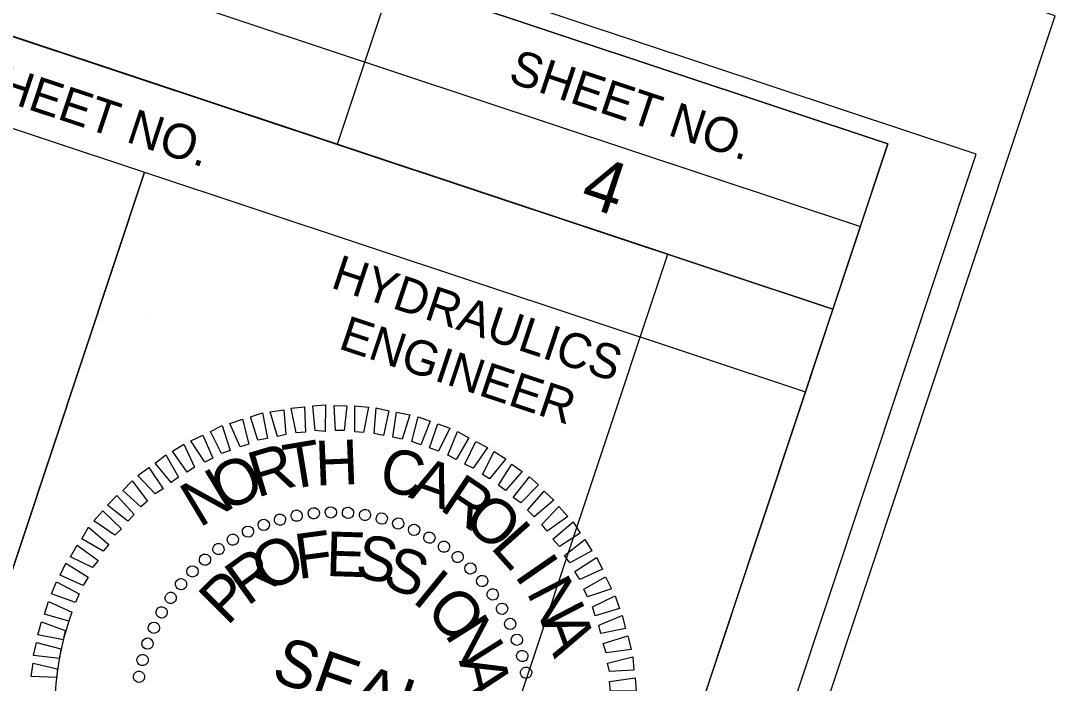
# Model space of a CAD drawing. Extents: x 2296288 to 2297455, y 600637 to 601606.
# Drawn here: x 2297365.9 to 2297455, y 601229.6 to 601286.7 of the extents above; entities that cross this region are included whole.
import ezdxf

# ---------------------------------------------------------------- set-up
doc = ezdxf.new("R2010")
doc.units = 0
for name, color, linetype in [('Exist DTM Crownline Cogo Point CELL', 7, 'Continuous'), ('Exist DTM Drainline Cogo Comment', 7, 'Continuous'), ('Exist DTM Drainline Cogo Point CELL', 7, 'Continuous'), ('Exist Roads Curbs Cogo Number', 7, 'Continuous'), ('Exist Roads Curbs Cogo Point CELL', 7, 'Continuous'), ('Exist Roads EOP Cogo Point CELL', 7, 'Continuous'), ('Exist Roads EOP Other Cogo Elevation', 7, 'Continuous')]:
    doc.layers.add(name, color=color, linetype=linetype)

msp = doc.modelspace()

# ---------------------------------------------------------------- linework, layer by layer
at = {"layer": 'Exist DTM Crownline Cogo Point CELL'}
msp.add_arc((2297392.802, 601227.377), 23.962, 161.60824, 341.60824, dxfattribs=at)
at = {"layer": 'Exist DTM Drainline Cogo Comment'}
for p, q in [((2297324.329, 601306.788), (2297438.228, 601268.917)), ((2297321.963, 601299.671), (2297435.862, 601261.8)), ((2297321.963, 601299.671), (2297435.862, 601261.8)), ((2297397.893, 601290.232), (2297393.16, 601275.998)), ((2297435.862, 601261.8), (2297433.495, 601254.683))]:
    msp.add_line(p, q, dxfattribs=at)
for points in [[(2297440.604, 601276.062), (2296586.575, 601560.023), (2296387.802, 600962.203), (2297241.831, 600678.242)], [(2297326.705, 601313.933), (2297440.604, 601276.062), (2297435.862, 601261.8), (2297321.963, 601299.671)], [(2297319.596, 601292.554), (2297376.56, 601273.614), (2297355.263, 601209.561), (2297298.299, 601228.501)], [(2297376.56, 601273.614), (2297433.496, 601254.683), (2297412.199, 601190.63), (2297355.263, 601209.561)]]:
    msp.add_lwpolyline(points, close=True, dxfattribs=at)
at = {"layer": 'Exist DTM Drainline Cogo Point CELL'}
msp.add_lwpolyline([(2297421.637, 601266.561), (2296596.076, 601541.057), (2296406.768, 600971.704), (2297232.33, 600697.208)], close=True, dxfattribs=at)
at = {"layer": 'Exist Roads Curbs Cogo Number'}
msp.add_lwpolyline([(2297455.016, 601287.078), (2296496.225, 601605.872), (2296287.987, 600979.583), (2297246.777, 600660.79)], close=True, dxfattribs=at)
at = {"layer": 'Exist Roads Curbs Cogo Point CELL'}
msp.add_lwpolyline([(2297448.204, 601275.148), (2296499.377, 601590.629), (2296299.639, 600989.904), (2297248.465, 600674.423)], close=True, dxfattribs=at)
at = {"layer": 'Exist Roads EOP Other Cogo Elevation'}
for p, q in [((2297376.853, 601260.92), (2297376.853, 601260.92)), ((2297391.156, 601244.25), (2297391.156, 601244.25)), ((2297392.608, 601244.336), (2297392.608, 601244.336)), ((2297394.08, 601244.273), (2297394.08, 601244.273)), ((2297388.232, 601243.692), (2297388.232, 601243.692)), ((2297389.694, 601244.024), (2297389.694, 601244.024)), ((2297395.575, 601244.061), (2297395.575, 601244.061)), ((2297397.016, 601243.795), (2297397.016, 601243.795)), ((2297398.436, 601243.359), (2297398.436, 601243.359)), ((2297385.469, 601242.655), (2297385.469, 601242.655)), ((2297386.845, 601243.264), (2297386.845, 601243.264)), ((2297399.813, 601242.794), (2297399.813, 601242.794)), ((2297384.178, 601241.982), (2297384.178, 601241.982)), ((2297401.115, 601242.112), (2297401.115, 601242.112)), ((2297382.941, 601241.148), (2297382.941, 601241.148)), ((2297402.365, 601241.376), (2297402.365, 601241.376)), ((2297381.757, 601240.262), (2297381.757, 601240.262)), ((2297403.561, 601240.481), (2297403.561, 601240.481)), ((2297380.701, 601239.226), (2297380.701, 601239.226)), ((2297404.65, 601239.478), (2297404.65, 601239.478)), ((2297379.698, 601238.136), (2297379.698, 601238.136)), ((2297405.686, 601238.423), (2297405.686, 601238.423)), ((2297406.573, 601237.239), (2297406.573, 601237.239)), ((2297378.803, 601236.94), (2297378.803, 601236.94)), ((2297378.067, 601235.691), (2297378.067, 601235.691)), ((2297407.406, 601236.001), (2297407.406, 601236.001)), ((2297408.08, 601234.71), (2297408.08, 601234.71)), ((2297377.385, 601234.388), (2297377.385, 601234.388)), ((2297376.821, 601233.011), (2297376.821, 601233.011)), ((2297408.689, 601233.334), (2297408.689, 601233.334)), ((2297409.117, 601231.947), (2297409.117, 601231.947)), ((2297376.384, 601231.591), (2297376.384, 601231.591)), ((2297376.118, 601230.15), (2297376.118, 601230.15)), ((2297409.449, 601230.485), (2297409.449, 601230.485))]:
    msp.add_line(p, q, dxfattribs=at)
for points in [[(2297388.013, 601250.843), (2297387.403, 601252.966), (2297388.567, 601253.149), (2297388.75, 601251.025)], [(2297389.646, 601251.154), (2297389.218, 601253.288), (2297390.359, 601253.406), (2297390.447, 601251.208)], [(2297391.279, 601251.358), (2297391.064, 601253.492), (2297392.152, 601253.557), (2297392.143, 601251.284)], [(2297393.019, 601251.348), (2297392.921, 601253.515), (2297394.01, 601253.473), (2297393.766, 601251.349)], [(2297394.694, 601251.254), (2297394.693, 601253.495), (2297395.856, 601253.357), (2297395.42, 601251.19)], [(2297396.349, 601251.095), (2297396.518, 601253.315), (2297397.607, 601253.059), (2297397.149, 601250.935)], [(2297384.802, 601249.955), (2297383.936, 601251.95), (2297385.024, 601252.335), (2297385.549, 601250.169)], [(2297386.338, 601250.511), (2297385.696, 601252.538), (2297386.731, 601252.87), (2297387.17, 601250.661)], [(2297397.95, 601250.776), (2297398.279, 601252.943), (2297399.41, 601252.709), (2297398.75, 601250.616)], [(2297399.604, 601250.403), (2297400.136, 601252.538), (2297401.183, 601252.155), (2297400.362, 601250.116)], [(2297383.19, 601249.388), (2297382.25, 601251.266), (2297383.274, 601251.779), (2297383.948, 601249.634)], [(2297401.131, 601249.86), (2297401.823, 601251.942), (2297402.869, 601251.559), (2297401.889, 601249.573)], [(2297381.761, 601248.618), (2297380.564, 601250.474), (2297381.61, 601250.945), (2297382.444, 601248.96)], [(2297402.7, 601249.232), (2297403.521, 601251.271), (2297404.514, 601250.727), (2297403.426, 601248.848)], [(2297380.235, 601247.774), (2297378.985, 601249.577), (2297379.967, 601250.175), (2297380.875, 601248.201)], [(2297404.152, 601248.464), (2297405.122, 601250.418), (2297406.126, 601249.907), (2297404.889, 601248.113)], [(2297378.87, 601246.877), (2297377.503, 601248.54), (2297378.42, 601249.267), (2297379.489, 601247.347)], [(2297405.669, 601247.569), (2297406.681, 601249.544), (2297407.685, 601248.926), (2297406.288, 601247.185)], [(2297377.483, 601245.915), (2297376.009, 601247.472), (2297376.948, 601248.156), (2297378.187, 601246.321)], [(2297407.067, 601246.642), (2297408.208, 601248.468), (2297409.094, 601247.817), (2297407.665, 601246.194)], [(2297376.257, 601244.793), (2297374.697, 601246.201), (2297375.508, 601247.034), (2297376.843, 601245.274)], [(2297408.317, 601245.586), (2297409.724, 601247.359), (2297410.493, 601246.676), (2297408.979, 601245.117)], [(2297409.556, 601244.498), (2297410.985, 601246.122), (2297411.828, 601245.343), (2297410.143, 601243.912)], [(2297375.126, 601243.533), (2297373.386, 601244.93), (2297374.196, 601245.763), (2297375.681, 601244.131)], [(2297374.017, 601242.337), (2297372.223, 601243.574), (2297372.97, 601244.428), (2297374.593, 601242.892)], [(2297410.784, 601243.272), (2297412.256, 601244.81), (2297413.035, 601243.946), (2297411.265, 601242.685)], [(2297411.746, 601241.992), (2297413.484, 601243.477), (2297414.093, 601242.527), (2297412.322, 601241.373)], [(2297373.026, 601240.959), (2297371.179, 601242.036), (2297371.754, 601243.018), (2297373.506, 601241.547)], [(2297412.739, 601240.594), (2297414.51, 601241.962), (2297415.108, 601240.98), (2297413.199, 601239.944)], [(2297372.098, 601239.561), (2297370.198, 601240.477), (2297370.784, 601241.491), (2297372.578, 601240.148)], [(2297371.299, 601238.012), (2297369.313, 601238.886), (2297369.803, 601239.932), (2297371.715, 601238.728)], [(2297413.626, 601239.197), (2297415.493, 601240.426), (2297416.006, 601239.402), (2297414.075, 601238.514)], [(2297370.628, 601236.528), (2297368.567, 601237.285), (2297368.983, 601238.32), (2297370.947, 601237.276)], [(2297414.406, 601237.693), (2297416.284, 601238.74), (2297416.797, 601237.716), (2297414.716, 601237.021)], [(2297415.144, 601236.167), (2297417.096, 601237.118), (2297417.481, 601236.03), (2297415.379, 601235.378)], [(2297370.063, 601234.938), (2297367.95, 601235.534), (2297368.312, 601236.623), (2297370.319, 601235.706)], [(2297415.689, 601234.599), (2297417.706, 601235.422), (2297418.006, 601234.291), (2297415.871, 601233.862)], [(2297369.563, 601233.326), (2297367.396, 601233.762), (2297367.694, 601234.872), (2297369.754, 601234.116)], [(2297416.085, 601233.009), (2297418.187, 601233.661), (2297418.476, 601232.498), (2297416.321, 601232.219)], [(2297369.244, 601231.725), (2297367.013, 601231.969), (2297367.279, 601233.089), (2297369.371, 601232.536)], [(2297416.45, 601231.323), (2297418.616, 601231.847), (2297418.702, 601230.716), (2297416.632, 601230.586)], [(2297369.021, 601230.092), (2297366.801, 601230.154), (2297366.971, 601231.307), (2297369.052, 601230.828)], [(2297416.632, 601229.733), (2297418.841, 601230.065), (2297418.917, 601228.902), (2297416.718, 601228.922)]]:
    msp.add_lwpolyline(points, close=True, dxfattribs=at)
for centre, major_axis in [((2297388.247, 601243.682), (-0.131, 0.468)), ((2297389.685, 601244.017), (-0.089, 0.478)), ((2297391.147, 601244.225), (-0.047, 0.484)), ((2297392.622, 601244.305), (-0.005, 0.486)), ((2297394.098, 601244.257), (0.037, 0.485)), ((2297395.564, 601244.079), (0.079, 0.479)), ((2297397.01, 601243.775), (0.121, 0.471)), ((2297386.843, 601243.223), (-0.171, 0.455)), ((2297398.423, 601243.346), (0.161, 0.458)), ((2297399.793, 601242.795), (0.201, 0.443)), ((2297384.182, 601241.948), (-0.247, 0.418)), ((2297385.485, 601242.643), (-0.21, 0.438)), ((2297401.11, 601242.127), (0.239, 0.423)), ((2297382.945, 601241.141), (-0.283, 0.395)), ((2297402.364, 601241.347), (0.275, 0.401)), ((2297381.783, 601240.229), (-0.316, 0.369)), ((2297403.545, 601240.46), (0.308, 0.376)), ((2297380.705, 601239.22), (-0.347, 0.34)), ((2297404.645, 601239.474), (0.34, 0.347)), ((2297405.654, 601238.396), (0.369, 0.316)), ((2297379.719, 601238.121), (-0.376, 0.308)), ((2297378.832, 601236.94), (-0.401, 0.275)), ((2297406.565, 601237.234), (0.395, 0.283)), ((2297378.052, 601235.686), (-0.423, 0.239)), ((2297407.372, 601235.997), (0.418, 0.247)), ((2297377.384, 601234.369), (-0.443, 0.201)), ((2297408.068, 601234.694), (0.438, 0.21)), ((2297376.833, 601232.998), (-0.458, 0.161)), ((2297408.648, 601233.336), (0.455, 0.171)), ((2297376.404, 601231.585), (-0.471, 0.121)), ((2297409.107, 601231.932), (0.468, 0.131)), ((2297409.441, 601230.494), (0.478, 0.089)), ((2297376.1, 601230.14), (-0.479, 0.079))]:
    msp.add_ellipse(centre, major_axis=major_axis, ratio=0.999708, dxfattribs=at)

# ---------------------------------------------------------------- texts
at = {"layer": 'Exist DTM Drainline Cogo Comment'}
for s, height, p in [('R/W SHEET NO.', 3.00007, (2297352.674, 601283.642)), ('SHEET NO.', 3.0001, (2297407.794, 601281.407)), ('HYDRAULICS', 3.0001, (2297392.515, 601263.693)), ('ENGINEER', 3.0001, (2297393.174, 601258.447))]:
    msp.add_text(s, height=height, rotation=341.60824, dxfattribs=at).set_placement(p)
at = {"layer": 'Exist Roads EOP Cogo Point CELL'}
msp.add_text('4', height=4.5, rotation=341.60824, dxfattribs=at).set_placement((2297413.937, 601270.86))
at = {"layer": 'Exist Roads EOP Other Cogo Elevation'}
for s, height, rotation, p in [('T', 3.884, 9.42801, (2297388.903, 601246.244)), ('H', 3.854, 2.22772, (2297391.336, 601246.608)), ('R', 3.911, 16.62875, (2297386.256, 601245.559)), ('C', 3.811, 347.82811, (2297396.63, 601246.271)), ('O', 3.929, 23.82998, (2297383.386, 601244.308)), ('A', 3.806, 340.62856, (2297399.224, 601245.622)), ('N', 3.933, 31.03174, (2297381.296, 601242.94)), ('R', 3.835, 326.22934, (2297401.871, 601244.599)), ('O', 3.862, 319.02941, (2297403.857, 601243.405)), ('L', 3.892, 311.82912, (2297406.282, 601241.283)), ('F', 3.876, 7.57528, (2297389.794, 601238.549)), ('E', 3.839, 358.21931, (2297392.163, 601238.829)), ('O', 3.932, 26.28948, (2297387.052, 601237.363)), ('S', 3.812, 348.86385, (2297394.597, 601238.766)), ('R', 3.927, 35.64789, (2297385.41, 601236.166)), ('S', 3.806, 339.50864, (2297396.913, 601238.032)), ('I', 3.916, 304.62838, (2297408.365, 601238.884)), ('P', 3.897, 45.00713, (2297383.703, 601234.457)), ('I', 3.855, 320.79785, (2297399.519, 601236.668)), ('N', 3.931, 297.42715, (2297409.412, 601237.433)), ('O', 3.893, 311.44173, (2297400.651, 601235.793)), ('N', 3.923, 302.08485, (2297402.37, 601233.799)), ('A', 3.931, 290.2254, (2297410.673, 601234.915)), ('SEAL', 4.0489, 340.60824, (2297387.346, 601229.903)), ('A', 3.916, 283.36851, (2297403.642, 601231.527))]:
    msp.add_text(s, height=height, rotation=rotation, dxfattribs=at).set_placement(p)

doc.saveas('drawing.dxf')
